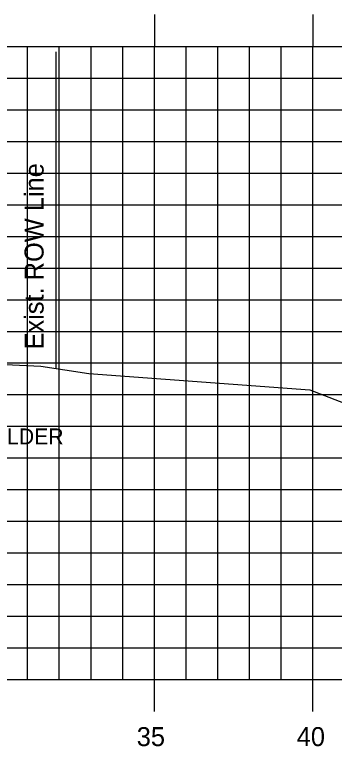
# Model space of a CAD drawing. Extents: x 859352 to 859522, y 366268 to 366378.
# Drawn here: x 859465.72 to 859475.8, y 366335.13 to 366358.24 of the extents above; entities that cross this region are included whole.
import ezdxf

# ---------------------------------------------------------------- set-up
doc = ezdxf.new("R2010")
doc.units = 0
for name, color, linetype in [('D_Text_Monospaced', 7, 'Continuous'), ('E_ROW_Line', 7, 'Continuous'), ('H_V ANNOTATION', 7, 'Continuous'), ('MAJOR', 7, 'Continuous'), ('MINOR', 7, 'Continuous'), ('S_Roadway_Centerline', 7, 'Continuous')]:
    doc.layers.add(name, color=color, linetype=linetype)

msp = doc.modelspace()

# ---------------------------------------------------------------- linework, layer by layer
at = {"layer": 'E_ROW_Line'}
msp.add_line((859467.033, 366347.062), (859467.033, 366357.062), dxfattribs=at)
at = {"layer": 'MAJOR'}
for p, q in [((859470.129, 366358.238), (859470.129, 366357.236)), ((859475.129, 366358.238), (859475.129, 366357.236)), ((859365.129, 366357.236), (859505.129, 366357.236)), ((859365.129, 366357.236), (859505.129, 366357.236)), ((859470.129, 366337.236), (859470.129, 366357.236)), ((859475.129, 366337.236), (859475.129, 366357.236)), ((859365.129, 366352.236), (859505.129, 366352.236)), ((859365.129, 366347.236), (859505.129, 366347.236)), ((859365.129, 366342.236), (859505.129, 366342.236)), ((859365.129, 366337.236), (859505.129, 366337.236)), ((859365.129, 366337.236), (859505.129, 366337.236)), ((859470.129, 366336.234), (859470.129, 366337.236)), ((859475.129, 366336.234), (859475.129, 366337.236))]:
    msp.add_line(p, q, dxfattribs=at)
at = {"layer": 'MINOR'}
for p, q in [((859466.129, 366337.236), (859466.129, 366357.236)), ((859467.129, 366337.236), (859467.129, 366357.236)), ((859468.129, 366337.236), (859468.129, 366357.236)), ((859469.129, 366337.236), (859469.129, 366357.236)), ((859471.129, 366337.236), (859471.129, 366357.236)), ((859472.129, 366337.236), (859472.129, 366357.236)), ((859473.129, 366337.236), (859473.129, 366357.236)), ((859474.129, 366337.236), (859474.129, 366357.236)), ((859365.129, 366356.236), (859505.129, 366356.236)), ((859365.129, 366355.236), (859505.129, 366355.236)), ((859365.129, 366354.236), (859505.129, 366354.236)), ((859365.129, 366353.236), (859505.129, 366353.236)), ((859365.129, 366351.236), (859505.129, 366351.236)), ((859365.129, 366350.236), (859505.129, 366350.236)), ((859365.129, 366349.236), (859505.129, 366349.236)), ((859365.129, 366348.236), (859505.129, 366348.236)), ((859365.129, 366346.236), (859505.129, 366346.236)), ((859365.129, 366345.236), (859505.129, 366345.236)), ((859365.129, 366344.236), (859505.129, 366344.236)), ((859365.129, 366343.236), (859505.129, 366343.236)), ((859365.129, 366341.236), (859505.129, 366341.236)), ((859365.129, 366340.236), (859505.129, 366340.236)), ((859365.129, 366339.236), (859505.129, 366339.236)), ((859365.129, 366339.236), (859505.129, 366339.236)), ((859365.129, 366338.236), (859505.129, 366338.236))]:
    msp.add_line(p, q, dxfattribs=at)
at = {"layer": 'S_Roadway_Centerline'}
msp.add_lwpolyline([(859445.818, 366348.091), (859453.662, 366347.816), (859453.944, 366347.99), (859454.346, 366348.245), (859456.203, 366348.22), (859462.014, 366347.49), (859464.97, 366347.207), (859466.549, 366347.136), (859468.064, 366346.907), (859475.033, 366346.391), (859476.741, 366345.729)], dxfattribs=at)

# ---------------------------------------------------------------- texts
at = {"layer": 'D_Text_Monospaced'}
msp.add_text('EXIST. 2" BOX ALDER', height=0.49998, dxfattribs=at).set_placement((859460.338, 366344.668))
at = {"layer": 'E_ROW_Line'}
msp.add_text('Exist. ROW Line', height=0.6, rotation=90, dxfattribs=at).set_placement((859466.633, 366347.662))
at = {"layer": 'H_V ANNOTATION'}
for s, p in [('35', (859469.57, 366335.136)), ('40', (859474.616, 366335.136))]:
    msp.add_text(s, height=0.6, dxfattribs=at).set_placement(p)

doc.saveas('drawing.dxf')
